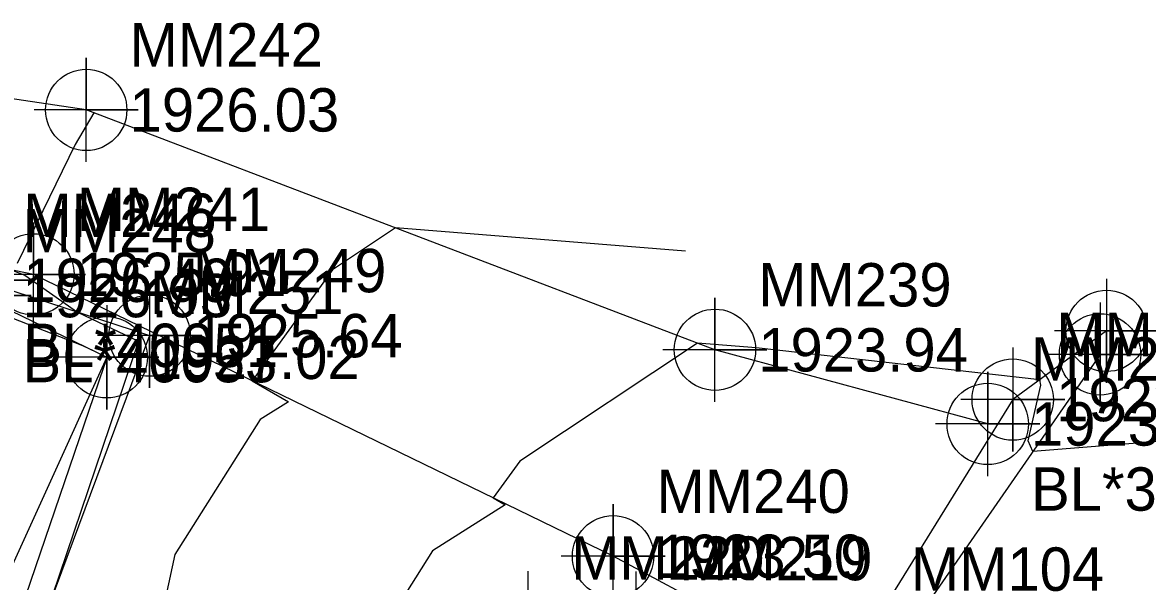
# Model space of a CAD drawing. Extents: x 1004378 to 1005103, y 553854 to 554288.
# Drawn here: x 1004979.8 to 1005044.7, y 554252.9 to 554285.1 of the extents above; entities that cross this region are included whole.
import ezdxf

# ---------------------------------------------------------------- set-up
doc = ezdxf.new("R2010")
doc.units = 0
for name, color, linetype in [('DTM Contours Major', 7, 'Continuous'), ('DTM Contours Minor', 7, 'Continuous'), ('Exist DTM Breakline', 7, 'Continuous'), ('Exist DTM Breakline Cogo Comment', 7, 'Continuous'), ('Exist DTM Breakline Cogo Elevation', 7, 'Continuous'), ('Exist DTM Breakline Cogo Number', 7, 'Continuous'), ('Exist DTM Breakline Cogo Point CELL', 7, 'Continuous'), ('Exist DTM Crownline', 7, 'Continuous'), ('Exist Roads EOP', 7, 'Continuous'), ('Exist Roads EOP Cogo Elevation', 7, 'Continuous'), ('Exist Roads EOP Cogo Number', 7, 'Continuous'), ('Exist Roads EOP Cogo Point CELL', 7, 'Continuous'), ('Exist Roads Soil', 7, 'Continuous'), ('Exist Roads Soil Cogo Comment', 7, 'Continuous'), ('Exist Roads Soil Cogo Elevation', 7, 'Continuous'), ('Exist Roads Soil Cogo Number', 7, 'Continuous'), ('Exist Roads Soil Cogo Point CELL', 7, 'Continuous')]:
    doc.layers.add(name, color=color, linetype=linetype)

msp = doc.modelspace()

# ---------------------------------------------------------------- linework, layer by layer
at = {"layer": 'DTM Contours Major'}
msp.add_lwpolyline([(1005018.059, 554271.971), (1005001.339, 554273.303), (1004997.708, 554270.886), (1004993.064, 554264.498), (1004995.16, 554263.287), (1004993.526, 554262.254), (1004988.609, 554254.469), (1004986.224, 554243.456), (1004985.222, 554236.535), (1004988.837, 554237.778), (1004993.872, 554231.637), (1004993.15, 554227.832), (1004992.988, 554222.697), (1004992.231, 554219.939), (1004990.684, 554217.999), (1004989.751, 554205.001)], dxfattribs=at)
at = {"layer": 'DTM Contours Minor'}
for points in [[(1004983.94, 554279.942), (1004982.863, 554278.109), (1004979.529, 554271.254)], [(1004979.178, 554270.892), (1004979.965, 554270.572), (1004983.011, 554268.448), (1004986.513, 554266.767), (1004981.55, 554252.068), (1004978.949, 554240.061)], [(1004976.979, 554268.984), (1004983.286, 554266.522), (1004984.471, 554265.976), (1004984.714, 554265.859), (1004984.509, 554265.252), (1004975.486, 554238.886)], [(1005049.674, 554261.493), (1005048.336, 554262.162), (1005048.391, 554261.154), (1005047.971, 554261.002), (1005047.219, 554261.151), (1005038.078, 554260.42), (1005037.81, 554261.029), (1005038.533, 554264.244), (1005038.474, 554264.547), (1005022.134, 554266.393), (1005018.739, 554266.663), (1005008.512, 554259.857), (1005006.97, 554257.736), (1005007.666, 554257.334), (1005003.478, 554254.686), (1004999.082, 554247.727), (1005001.345, 554242.184), (1004999.666, 554238.402), (1004998.854, 554234.12), (1004998.544, 554224.321), (1004997.101, 554219.058), (1004994.148, 554215.354), (1004993.153, 554201.493), (1004985.717, 554187.945)]]:
    msp.add_lwpolyline(points, dxfattribs=at)
at = {"layer": 'Exist DTM Breakline'}
msp.add_line((1005041.953, 554266.011), (1005027.535, 554245.207), dxfattribs=at)
for points in [[(1004977.38, 554270.285), (1004987.161, 554267.094), (1004974.231, 554232.47), (1004965.01, 554203.394)], [(1004977.332, 554269.403), (1004984.686, 554265.845), (1004970.343, 554234.297), (1004960.488, 554206.483)]]:
    msp.add_lwpolyline(points, dxfattribs=at)
at = {"layer": 'Exist DTM Breakline Cogo Point CELL'}
for points in [[(1004977.38, 554273.285), (1004977.38, 554267.285), (1004977.38, 554270.285), (1004980.38, 554270.285), (1004974.38, 554270.285)], [(1004977.332, 554272.403), (1004977.332, 554266.403), (1004977.332, 554269.403), (1004980.332, 554269.403), (1004974.332, 554269.403)], [(1004987.161, 554270.094), (1004987.161, 554264.094), (1004987.161, 554267.094), (1004990.161, 554267.094), (1004984.161, 554267.094)], [(1005041.953, 554269.011), (1005041.953, 554263.011), (1005041.953, 554266.011), (1005044.953, 554266.011), (1005038.953, 554266.011)], [(1004984.686, 554268.845), (1004984.686, 554262.845), (1004984.686, 554265.845), (1004987.686, 554265.845), (1004981.686, 554265.845)], [(1005008.958, 554253.519), (1005008.958, 554247.519), (1005008.958, 554250.519), (1005011.958, 554250.519), (1005005.958, 554250.519)], [(1005015.189, 554253.493), (1005015.189, 554247.493), (1005015.189, 554250.493), (1005018.189, 554250.493), (1005012.189, 554250.493)]]:
    msp.add_lwpolyline(points, dxfattribs=at)
for centre in [(1004987.161, 554267.094), (1005041.953, 554266.011), (1004984.686, 554265.845)]:
    msp.add_circle(centre, 2.344, dxfattribs=at)
at = {"layer": 'Exist DTM Crownline'}
msp.add_spline([(1005050.587, 554258.044), (1005028.479, 554219.945), (1005017.046, 554183.931), (1005013.967, 554147.492), (1005013.771, 554103.753), (1005015.769, 554055.214)], degree=3, dxfattribs=at)
at = {"layer": 'Exist Roads EOP'}
msp.add_lwpolyline([(1005042.326, 554267.369), (1005036.922, 554263.41), (1005028.544, 554249.886), (1005026.381, 554243.671)], dxfattribs=at)
at = {"layer": 'Exist Roads EOP Cogo Point CELL'}
for points in [[(1005042.326, 554270.369), (1005042.326, 554264.369), (1005042.326, 554267.369), (1005045.326, 554267.369), (1005039.326, 554267.369)], [(1005036.922, 554266.41), (1005036.922, 554260.41), (1005036.922, 554263.41), (1005039.922, 554263.41), (1005033.922, 554263.41)]]:
    msp.add_lwpolyline(points, dxfattribs=at)
for centre in [(1005042.326, 554267.369), (1005036.922, 554263.41)]:
    msp.add_circle(centre, 2.344, dxfattribs=at)
at = {"layer": 'Exist Roads Soil'}
for points in [[(1005035.476, 554262.003), (1005019.749, 554266.277), (1004983.505, 554280.108), (1004961.55, 554283.385)], [(1005026.922, 554247.386), (1005013.881, 554254.375), (1004980.46, 554270.626), (1004959.228, 554275.018)]]:
    msp.add_lwpolyline(points, dxfattribs=at)
at = {"layer": 'Exist Roads Soil Cogo Point CELL'}
for points in [[(1004983.505, 554277.108), (1004983.505, 554283.108), (1004983.505, 554280.108), (1004986.505, 554280.108), (1004980.505, 554280.108)], [(1004980.46, 554267.626), (1004980.46, 554273.626), (1004980.46, 554270.626), (1004983.46, 554270.626), (1004977.46, 554270.626)], [(1005019.749, 554263.277), (1005019.749, 554269.277), (1005019.749, 554266.277), (1005022.749, 554266.277), (1005016.749, 554266.277)], [(1005035.476, 554259.003), (1005035.476, 554265.003), (1005035.476, 554262.003), (1005038.476, 554262.003), (1005032.476, 554262.003)], [(1005013.881, 554251.375), (1005013.881, 554257.375), (1005013.881, 554254.375), (1005016.881, 554254.375), (1005010.881, 554254.375)]]:
    msp.add_lwpolyline(points, dxfattribs=at)
for centre in [(1004983.505, 554280.108), (1004980.46, 554270.626), (1005019.749, 554266.277), (1005035.476, 554262.003), (1005013.881, 554254.375)]:
    msp.add_circle(centre, 2.344, dxfattribs=at)

# ---------------------------------------------------------------- texts
at = {"layer": 'Exist DTM Breakline Cogo Comment'}
for s, p in [('BL*40051', (1004979.88, 554265.285)), ('BL*40053', (1004979.832, 554264.403))]:
    msp.add_text(s, height=2.5, dxfattribs=at).set_placement(p)
at = {"layer": 'Exist DTM Breakline Cogo Elevation'}
for s, p in [('1926.49', (1004979.88, 554269.035)), ('1926.93', (1004979.832, 554268.153)), ('1925.64', (1004989.661, 554265.844)), ('1927.02', (1004987.186, 554264.595))]:
    msp.add_text(s, height=2.5, dxfattribs=at).set_placement(p)
at = {"layer": 'Exist DTM Breakline Cogo Number'}
for s, p in [('MM246', (1004979.88, 554272.785)), ('MM248', (1004979.832, 554271.903)), ('MM249', (1004989.661, 554269.594)), ('MM251', (1004987.186, 554268.345)), ('MM220', (1005011.458, 554253.019)), ('MM219', (1005017.689, 554252.993))]:
    msp.add_text(s, height=2.5, dxfattribs=at).set_placement(p)
at = {"layer": 'Exist Roads EOP Cogo Elevation'}
msp.add_text('1923.80', height=2.5, dxfattribs=at).set_placement((1005039.422, 554262.16))
at = {"layer": 'Exist Roads EOP Cogo Number'}
for s, p in [('MM103', (1005039.422, 554265.91)), ('MM104', (1005031.044, 554252.386))]:
    msp.add_text(s, height=2.5, dxfattribs=at).set_placement(p)
at = {"layer": 'Exist Roads Soil Cogo Comment'}
msp.add_text('BL*30052', height=2.5, dxfattribs=at).set_placement((1005037.976, 554257.003))
at = {"layer": 'Exist Roads Soil Cogo Elevation'}
for s, p in [('1926.03', (1004986.005, 554278.858)), ('1925.91', (1004982.96, 554269.376)), ('1923.94', (1005022.249, 554265.027)), ('1923.63', (1005037.976, 554260.753)), ('1923.50', (1005016.381, 554253.125))]:
    msp.add_text(s, height=2.5, dxfattribs=at).set_placement(p)
at = {"layer": 'Exist Roads Soil Cogo Number'}
for s, p in [('MM242', (1004986.005, 554282.608)), ('MM241', (1004982.96, 554273.126)), ('MM239', (1005022.249, 554268.777)), ('MM238', (1005037.976, 554264.503)), ('MM240', (1005016.381, 554256.875))]:
    msp.add_text(s, height=2.5, dxfattribs=at).set_placement(p)

doc.saveas('drawing.dxf')
